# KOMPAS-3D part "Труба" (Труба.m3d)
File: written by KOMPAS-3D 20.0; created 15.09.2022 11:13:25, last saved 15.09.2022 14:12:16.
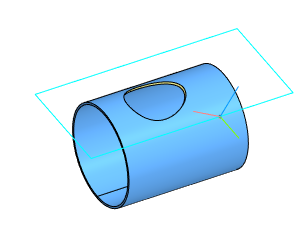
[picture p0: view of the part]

Document properties: Полное имя файла: D:\YAKOVLEV\ПРОЕКТЫ\ДЦ-2. ДП-7 Газопровод Окожушивание\ПРОБА Соединение труб. Окожушивание\Труба.m3d

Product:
- Part/product: Труба
    Материал: Сталь 45  ГОСТ 1050-2013 (density 7810 kg/m3)
    Масса: 4519.05

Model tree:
1. Плоскость под углом:1
     Угол = 30
2. Эскиз:1
3. Обечайка:1
     Расстояние 1 = 2500; Толщина листового тела = 40; Радиус сгиба = 960; Коэффициент = 0.4; Величина сгиба = 10; Зазор = 0.01
4. Эскиз:2  (with: Обечайка:1)
5. Вырез в листовом теле:2
     Глубина выреза = 2220
6. Касательная плоскость:1  (with: Обечайка:1)
7. Развертка  (labels: Сталь 45  ГОСТ 1050-2013)

Expressions: v83*2
Referenced files in D:\YAKOVLEV\ПРОЕКТЫ\ДЦ-2. ДП-7 Газопровод Окожушивание\ПРОБА Соединение труб. Окожушивание\: Соединение труб.a3d
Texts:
  Соединение труб. Окожушивание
